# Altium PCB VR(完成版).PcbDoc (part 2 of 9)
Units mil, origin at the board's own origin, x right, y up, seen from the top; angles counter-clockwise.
Board outline 2839.68 x 2020.7 mil, 6 copper layers (TOP, GND02, SIN03, SIN04, PWR05, BOTTOM); 494 components, 404 nets, 7124 pads, 1123 vias.
Unrouted connection lines stored in the file: 10.
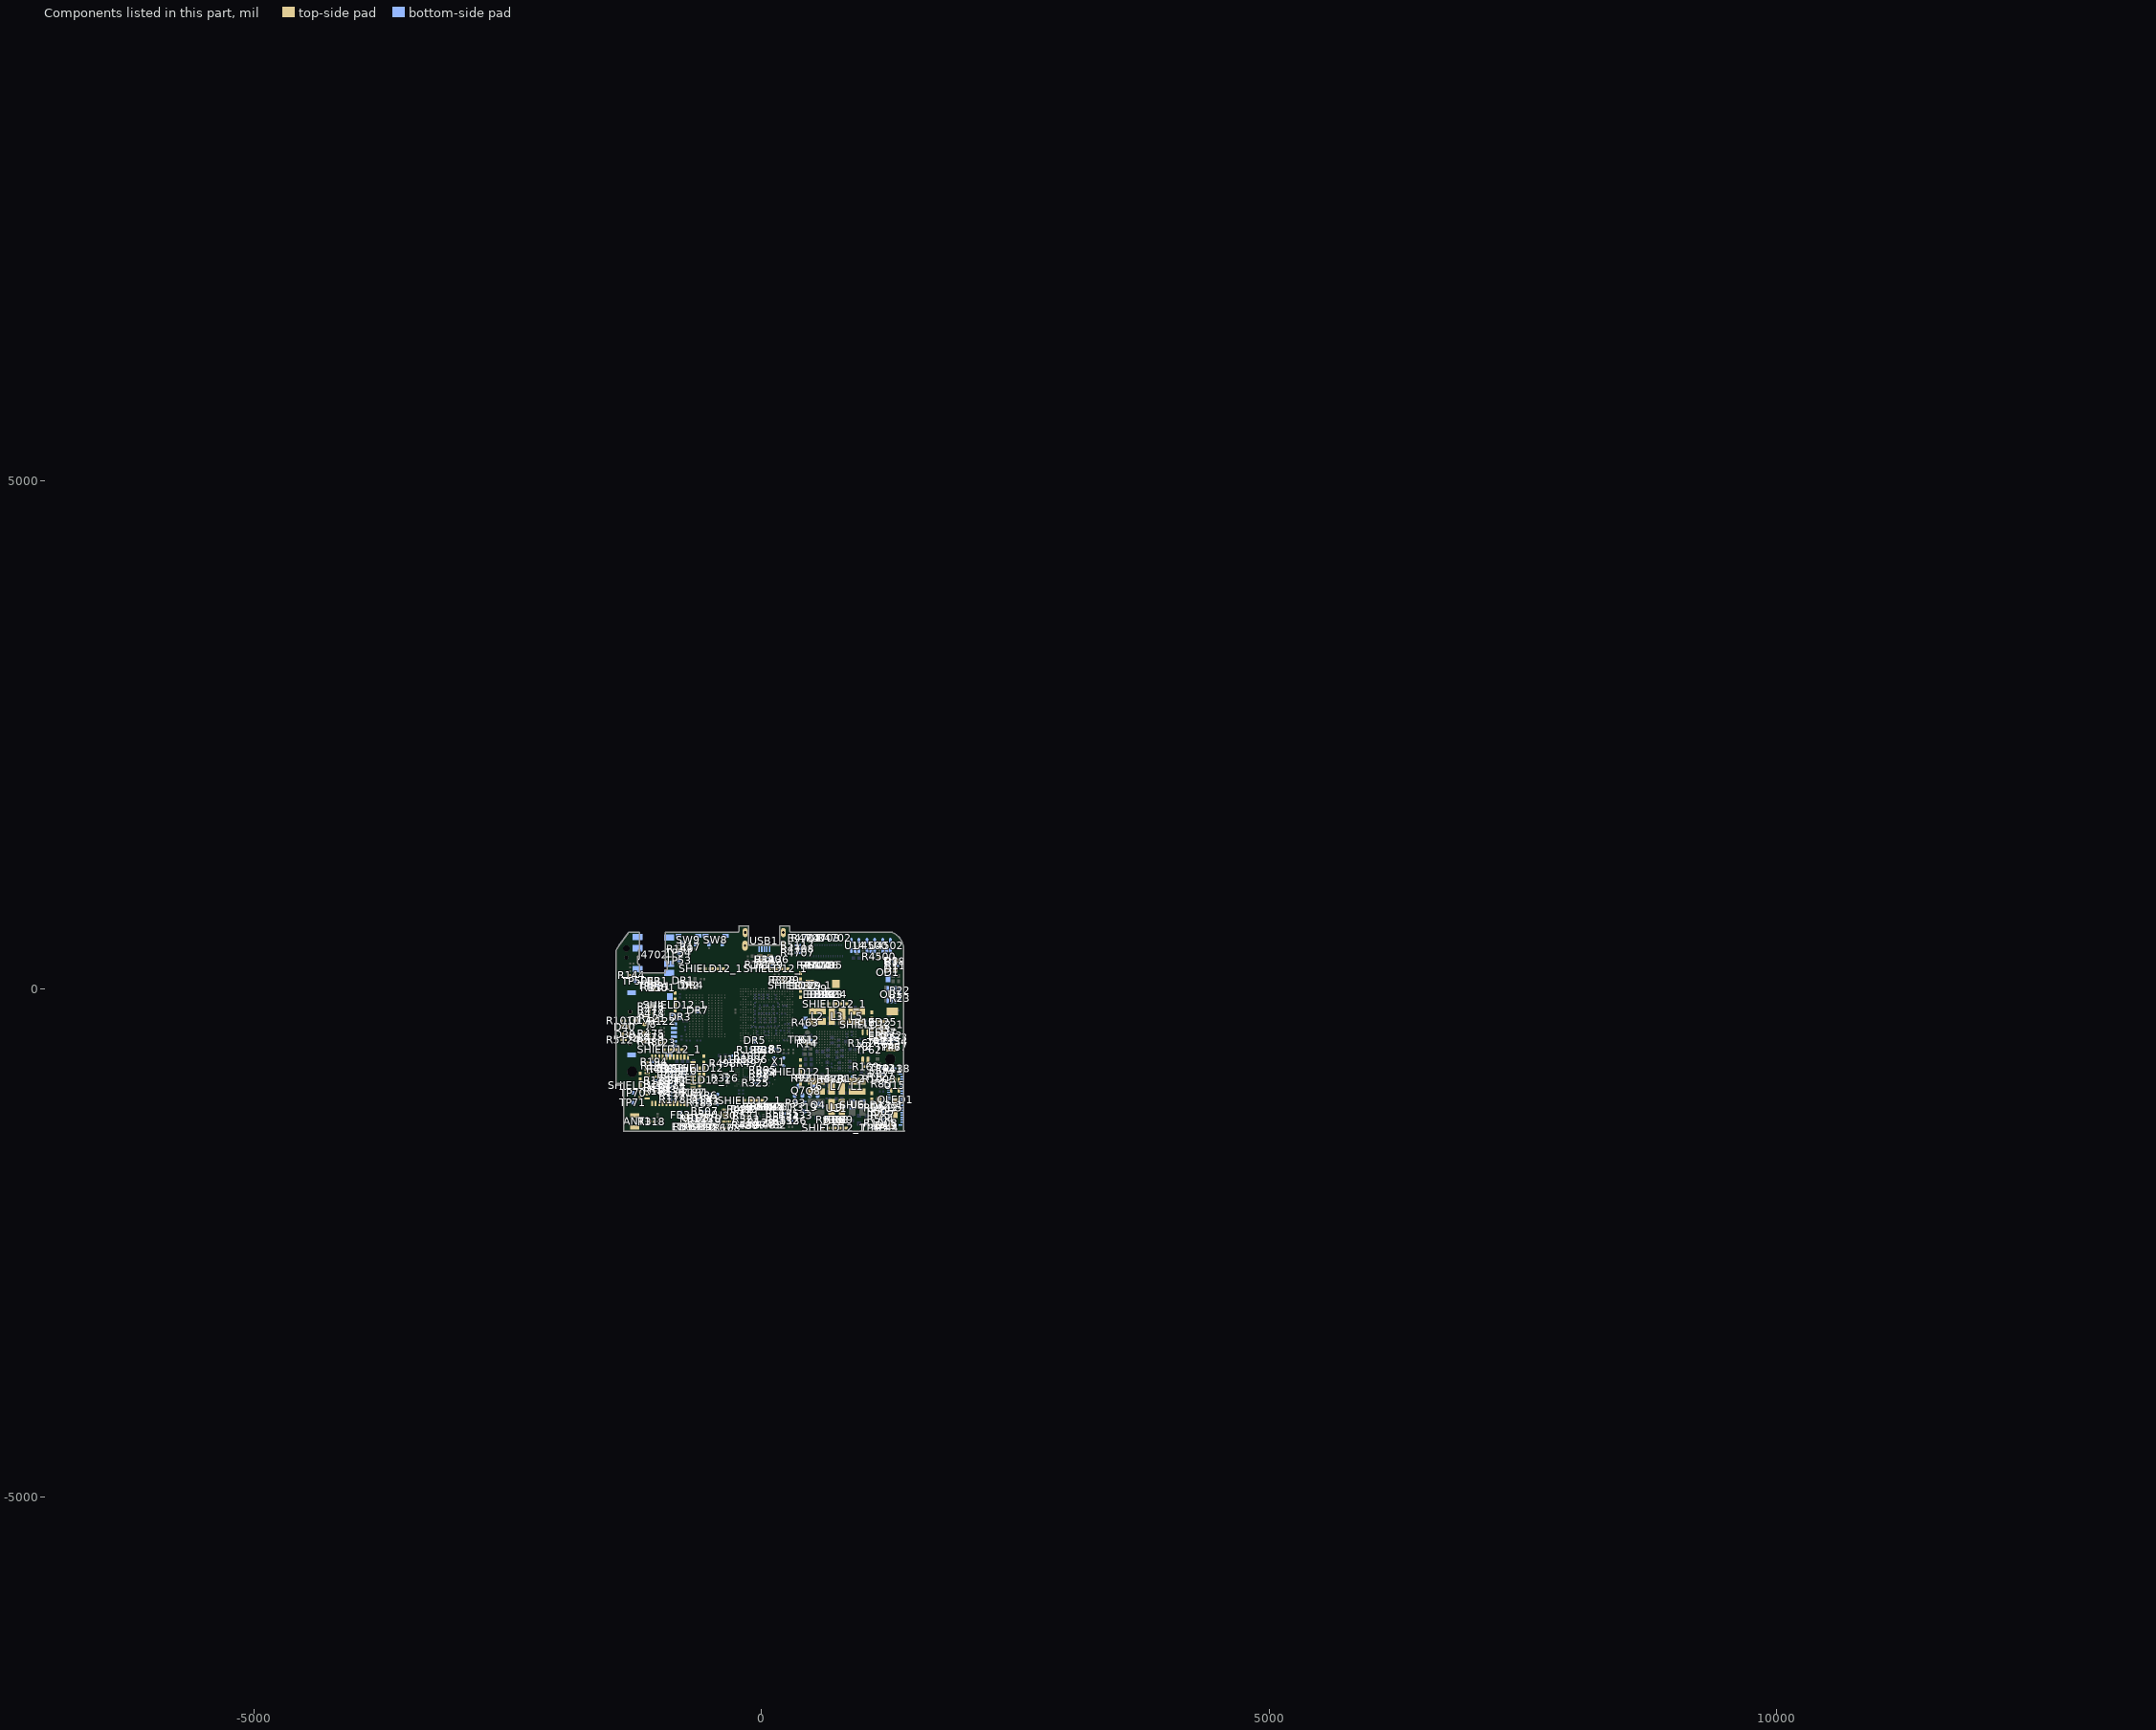
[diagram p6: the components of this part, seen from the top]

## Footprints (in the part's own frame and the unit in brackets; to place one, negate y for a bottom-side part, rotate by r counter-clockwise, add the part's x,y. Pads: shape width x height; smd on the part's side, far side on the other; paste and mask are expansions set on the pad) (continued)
CON2-WIFI-PT4 [mil]
  rect 41.34x41.34 smd: 1(0,30.02)
  rect 41.34x86.61 smd: 2(-58.07,-30.02) 3(58.07,-30.02)
  silkscreen extent -51,-93 51,84
CON39-PT0_6H1_8B [mm] "CON39-PT0_6H1_8B"
  rect 0.3x0.8 smd: 1(-5.7,1.64) 2(-5.4,-1.64) 3(-5.1,1.64) 4(-4.8,-1.64) 5(-4.5,1.64) 6(-4.2,-1.64) 7(-3.9,1.64) 8(-3.6,-1.64) 9(-3.3,1.64) 10(-3,-1.64) 11(-2.7,1.64) 12(-2.4,-1.64) 13(-2.1,1.64) 14(-1.8,-1.64) 15(-1.5,1.64) 16(-1.2,-1.64) 17(-0.9,1.64) 18(-0.6,-1.64) 19(-0.3,1.64) 20(0,-1.64) 21(0.3,1.64) 22(0.6,-1.64) 23(0.9,1.64) 24(1.2,-1.64) 25(1.5,1.64) 26(1.8,-1.64) 27(2.1,1.64) 28(2.4,-1.64) 29(2.7,1.64) 30(3,-1.64) 31(3.3,1.64) 32(3.6,-1.64) 33(3.9,1.64) 34(4.2,-1.64) 35(4.5,1.64) 36(4.8,-1.64) 37(5.1,1.64) 38(5.4,-1.64) 39(5.7,1.64)
  rect 0.35x1 smd: 40(6.35,1.265) 41(-6.35,1.265)
  silkscreen extent -6.65,-1.7 6.65,2.83
CRY-TSX3225 [mil] "CRY-TSX3225"
  oct 33.3x33.3 smd: 1(-37.99,47.83) 2(-37.99,-47.83) 3(37.99,-47.83) 4(37.99,47.83)
  silkscreen extent -90,-67 53,67
DFN8P0_65B2_00X2_00H0_75 [mm]
  rect 0.6x0.4 smd: 1(-1.03,0.65) 2(-1.03,0) 3(-1.03,-0.65) 4(1.03,-0.65) 5(1.03,0) 6(1.03,0.65)
  rect 0.6x0.3 smd: 7(0,-0.65)
  rect 1.05x1 smd: 8(0,0.3)
  silkscreen extent -2.15,-1.14 1.6,1.14
E0402N [mm]
  rect 0.51x0.51 smd: 1(-0.41,0) 2(0.41,0)
  silkscreen extent -1.14,-0.63 0.91,0.64
FPC4-PT1_25-3_8X10H4_6B [mm] "FPC4-PT1_25-3_8X10H4_6B"
  rect 0.85x2.75 smd: 1(-1.875,1.46) 2(-0.625,1.46) 3(0.625,1.46) 4(1.875,1.46)
  rect 2x2.8 smd: 5(-4.5,-1.44) 6(4.5,-1.44)
  silkscreen extent -5,-2.34 5,2.82
FPC8-PT0.5-H1_9A [mm]
  oval 0.3x1.25 smd: 1(0,0) 2(0.5,0) 3(1,0) 4(1.5,0) 5(2,0) 6(2.5,0)
  rect 2x2 smd: 7(4.5,2.29) 8(-2,2.29)
  silkscreen extent -2.99,-1.05 5.48,4.5
L0402 [mm]
  rect 0.51x0.51 smd: 1(-0.41,0) 2(0.41,0)
  silkscreen extent -0.7,-0.5 0.7,0.5
L0603 [mm]
  rect 0.76x0.8 smd: 1(-0.76,0) 2(0.76,0)
  silkscreen extent -1.15,-0.7 1.15,0.7
L3518 [mil] "L3518"
  oval 62.99x110.24 smd: 1(-51.21,0.03) 2(51.15,0.03)
  silkscreen extent -87,-63 87,63
L4018 [mm]
  rect 1.6x4.2 smd: 1(-1.3,0) 2(1.3,0)
  silkscreen extent -2.25,-2.25 2.25,2.25, body extent -1.7,-2.1 1.79,2.09, height 2.2
LED0603 [mm]
  rect 1x1 smd: 1(0.85,0) 2(-0.85,0)
  silkscreen extent -2.28,-0.8 1.65,1.44
LED0805 [mm]
  rect 1.2x1.2 smd: 1(0.95,0) 2(-0.95,0)
  silkscreen extent -2.42,-0.9 1.85,1.49
MICROSD_SLOT [mm]
  rect 0.7x1.6 smd: 1(-2.25,-5.5) 2(-1.15,-5.5) 3(-0.05,-5.5) 4(1.05,-5.5) 5(2.15,-5.5) 6(3.25,-5.5) 7(4.35,-5.5) 8(5.45,-5.5) 9(6.55,-5.5)
  rect 1x1.8 smd: 10(7.75,-4.2)
  rect 1.6x1.5 smd: 11(-6.85,-4.45)
  rect 1.2x2.2 smd: 12(-7.75,5.1) 13(7.75,5.1)
  round 1 hole 1 unplated: ""(-3.05,5.5) ""(4.95,5.5)
  silkscreen extent -8.08,-5 8.08,9.7
MIRCO_USB-5PH3A_DIP [mm] "MIRCO_USB-5PH3A_DIP"
  rect 0.4x1.5 smd: 1(1.3,-2.075) 2(0.65,-2.075) 3(0,-2.075) 4(-0.65,-2.075) 5(-1.3,-2.075)
  oval 1.35x2.5 hole 0.55 slot 1.7 at 90 deg: 6(4.825,-1.225) 7(-4.825,-1.225)
  oval 1.25x2.3 hole 0.65 slot 1.7 at 90 deg: 8(-4.775,2.075) 9(4.775,2.075)
  Keep-Out Layer lines w0.127: 3.809,-0.918 3.809,3.082 ; 3.809,-0.918 -3.791,-0.918 ; 3.809,-0.918 3.809,3.082 ; 3.809,-0.918 -3.791,-0.918 ; 3.809,-0.918 3.809,3.082 ; 3.809,-0.918 -3.791,-0.918 ; 3.809,-0.918 3.809,3.082 ; 3.809,-0.918 -3.791,-0.918 ; 3.809,-0.918 3.809,3.082 ; 3.809,-0.918 -3.791,-0.918 ; 3.809,-0.918 -3.791,-0.918 ; 3.809,-0.918 3.809,3.082 ; -3.791,-0.918 -3.791,3.082 ; -3.791,-0.918 -3.791,3.082 ; -3.791,-0.918 -3.791,3.082 ; -3.791,-0.918 -3.791,3.082 ; -3.791,-0.918 -3.791,3.082 ; -3.791,-0.918 -3.791,3.082
  silkscreen extent -3.81,-1.82 3.8,4.03
MSOP8-PT1-27A [mm]
  rect 1.2x0.4 smd: 1(-2.25,0.975) 2(-2.25,0.325) 3(-2.25,-0.325) 4(-2.25,-0.975) 5(2.25,-0.975) 6(2.25,-0.325) 7(2.25,0.325) 8(2.25,0.975)
  silkscreen extent -1.5,-1.47 1.5,1.48, body extent -1.5,-1.47 1.5,1.48, height 1.2
PJ342 [mm]
  rect 2.5x1.6 smd: 2(-3.95,-4.488) 3(3.95,-4.313) 4(-3.95,-1.663) 5(-3.95,3.538) 6(3.95,2.237) 7(3.95,4.488)
  silkscreen extent -3.7,-9.11 3.7,4.99
QFN24-3X3 [mm] "PS-MPU-6515A-00"
  oval 0.2x0.6 smd: 1(-1,-1.5) 2(-0.6,-1.5) 3(-0.2,-1.5) 4(0.2,-1.5) 5(0.6,-1.5) 6(1,-1.5) 13(1,1.5) 14(0.6,1.5) 15(0.2,1.5) 16(-0.2,1.5) 17(-0.6,1.5) 18(-1,1.5)
  oval 0.6x0.2 smd: 7(1.5,-1) 8(1.5,-0.6) 9(1.5,-0.2) 10(1.5,0.2) 11(1.5,0.6) 12(1.5,1) 19(-1.5,1) 20(-1.5,0.6) 21(-1.5,0.2) 22(-1.5,-0.2) 23(-1.5,-0.6) 24(-1.5,-1)
  rect 1.54x1.7 smd: 25(0,0)
  silkscreen extent -1.6,-2 1.5,1.5
QFN44P0_90B12_00X12_00H1_50 [mm]
  rect 1.3x0.5 smd: 1(-5.775,4.5) 2(-5.775,3.6) 3(-5.775,2.7) 4(-5.775,1.8) 5(-5.775,0.9) 6(-5.775,0) 7(-5.775,-0.9) 8(-5.775,-1.8) 9(-5.775,-2.7) 10(-5.775,-3.6) 11(-5.775,-4.5) 23(5.775,-4.5) 24(5.775,-3.6) 25(5.775,-2.7) 26(5.775,-1.8) 27(5.775,-0.9) 28(5.775,0) 29(5.775,0.9) 30(5.775,1.8) 31(5.775,2.7) 32(5.775,3.6) 33(5.775,4.5)
  rect 0.5x1.3 smd: 12(-4.5,-5.775) 13(-3.6,-5.775) 14(-2.7,-5.775) 15(-1.8,-5.775) 16(-0.9,-5.775) 17(0,-5.775) 18(0.9,-5.775) 19(1.8,-5.775) 20(2.7,-5.775) 21(3.6,-5.775) 22(4.5,-5.775) 34(4.5,5.775) 35(3.6,5.775) 36(2.7,5.775) 37(1.8,5.775) 38(0.9,5.775) 39(0,5.775) 40(-0.9,5.775) 41(-1.8,5.775) 42(-2.7,5.775) 43(-3.6,5.775) 44(-4.5,5.775)
  round 0.6 smd: 45(-2.7,3.6) 46(-0.9,3.6) 47(0.9,3.6)
  silkscreen extent -6.8,-6.8 6.8,6.8, body extent -6,-6 6,6, height 1.6
R0402 [mil] "R0402"
  rect 23.62x23.62 smd: 1(-17.69,0) 2(17.69,0)
  silkscreen extent -33,-16 33,16
R0603 [mil] "R0603"
  rect 31.5x35.43 smd: 1(-28.06,0) 2(27.06,0)
  silkscreen extent -50,-24 50,24
R0805 [mm] "R0805"
  rect 1x1 smd: 1(-1,0) 2(1,0)
  silkscreen extent -1.8,-0.8 1.8,0.8
SOD123 [mm] "SOD123"
  rect 1.8x1.2 smd: 1(-1.6,0) 2(1.6,0)
  silkscreen extent -3.8,-0.9 2.8,1.6
sot23-5 [mm]
  rect 0.6x1.4 smd: 1(-0.95,-1.3) 2(0,-1.3) 3(0.95,-1.3) 4(0.95,1.3) 5(-0.95,1.3)
  silkscreen extent -1.5,-2.75 1.5,0.3
SOT23-5 [mm]
  rect 0.6x1.4 smd: 1(-0.95,-1.3) 2(0,-1.3) 3(0.95,-1.3) 4(0.95,1.3) 5(-0.95,1.3)
  silkscreen extent -2.1,-2.17 1.5,0.3
SOT23-6 [mm] "SOT23-6"
  oval 0.6x1.25 smd: 1(-0.95,-1.52) 2(0,-1.52) 3(0.95,-1.52) 4(0.95,1.53) 5(0,1.53) 6(-0.95,1.53)
  silkscreen extent -1.88,-1.54 1.5,0.86
SOT23_5H14A [mil] "SOT23_5H14A"
  oval 50x26 smd: 1(-50,37.5) 2(-50,0) 3(-50,-37.5) 4(50,-37.5) 5(50,37.5)
  silkscreen extent -86,-64 36,73
SOT-23 [mil] "SOT-23"
  oval 50x40 smd: 1(-45,37.5) 2(-45,-37.5) 3(45,0)
  silkscreen extent -29,-63 29,73
SW4_SMD [mm]
  rect 0.8x1.3 smd: 1(1.7,-0.975) 2(-1.7,-0.975)
  rect 1.5x1 smd: 3(-2.5,0.975) 4(2.5,0.975)
  round 0.7 hole 0.7 unplated: 5(-0.8,0.475) 6(0.8,0.475)
  silkscreen extent -2.33,-0.62 2.34,2.08
TEST2 [mm]
  rect 1.4x0.7 smd far side: 1(0,0)
  rect 0.8x0.7 smd far side: 2(-1.5,0) 4(1.5,0)
  rect 0.9x0.7 smd far side: 3(-3,0) 5(3,0)
TP40_SMD [mm] "TP40_SMD"
  round 1 smd: 1(0,0)
  silkscreen extent -0.6,-0.6 0.6,0.6
TP_SMD [mil] "TP_SMD"
  round 40 smd: 1(0,0)
  silkscreen extent -26,-26 26,26
XCOL-SMD [mm]
  round 0.5 on Top Overlay: 0(-2.223,0.653)
  oval 1.8x0.8 smd: 1(-3.5,0.647) 2(-3.5,-0.653)
  oval 1.5x0.5 smd: 3(3.5,0.647) 4(3.5,-0.553)
  silkscreen extent -2.6,-0.95 2.7,1.05, body extent -2.6,-0.95 2.7,1.05, height 1.5

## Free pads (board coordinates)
  round 39.37 hole 39.37 unplated: 0(-1329.63,307.82)
  round 62.99 hole 62.99 unplated: 0(-1329.63,398.37)
  round 102.36 hole 102.36 unplated: 0(-1270.58,-817.05) 0(1268.8,-692.18)
  round 11.8 on Drill Drawing: 1(-6737.21,-6759.26) 1(-6737.21,-6759.26) 1(-6737.21,9185.04) 1(-6737.21,9186.21) 1(-6146.65,-3215.96) 1(-6146.65,-263.2) 1(-6146.65,2689.56) 1(-6146.65,5642.33) 1(-5851.37,5524.22) 1(-5851.37,5524.22) 1(-5851.37,5642.33) 1(-5851.37,5760.44) 1(-5851.37,5760.44) 1(-5556.1,-6168.71) 1(-5556.1,-6168.71) 1(-5556.1,-3215.96) 1(-5556.1,-263.2) 1(-5556.1,2689.56) 1(-5556.1,5642.33) 1(-5556.1,5642.33) 1(-5556.1,8593.89) 1(-5556.1,8595.66) 1(-2603.35,-6759.26) 1(-2603.35,-6168.71) 1(-1507.86,8595.66) 1(-1507.86,9186.21) 1(349.41,-6759.26) 1(349.41,-6168.71) 1(1444.89,8595.66) 1(1444.89,9186.21) 1(3302.18,-6759.26) 1(3302.18,-6168.71) 1(4397.64,8595.66) 1(4397.64,9186.21) 1(6254.93,-6759.26) 1(6254.93,-6168.71) 1(6254.93,8595.66) 1(6254.93,9186.21) 1(7428.47,6343.47) 1(7428.47,6343.47) 1(7428.47,6433.23) 1(7428.47,6433.23) 1(7428.47,6693.47) 1(7428.47,6693.47) 1(7428.47,6783.23) 1(7428.47,6783.23) 1(7428.47,6843.47) 1(7428.47,6843.47) 1(7428.47,6933.23) 1(7428.47,6933.23) 1(7428.67,6198.47) 1(7428.67,6198.47) 1(7428.67,6288.23) 1(7428.67,6288.23) 1(7518.23,6343.47) 1(7518.23,6343.47) 1(7518.23,6433.23) 1(7518.23,6433.23) 1(7518.23,6693.47) 1(7518.23,6693.47) 1(7518.23,6783.23) 1(7518.23,6783.23) 1(7518.23,6843.47) 1(7518.23,6843.47) 1(7518.23,6933.23) 1(7518.23,6933.23) 1(7518.43,6198.47) 1(7518.43,6198.47) 1(7518.43,6288.23) 1(7518.43,6288.23) 1(8103.67,6043.47) 1(8103.67,6043.47) 1(8103.67,6133.23) 1(8103.67,6133.23) 1(8193.43,6043.47) 1(8193.43,6043.47) 1(8193.43,6133.23) 1(8193.43,6133.23) 1(8728.47,7293.47) 1(8728.47,7293.47) 1(8728.47,7383.23) 1(8728.47,7383.23) 1(8818.23,7293.47) 1(8818.23,7293.47) 1(8818.23,7383.23) 1(8818.23,7383.23) 1(9207.7,-6759.26) 1(9207.7,-6168.71) 1(9207.7,8595.66) 1(9207.7,9186.21) 1(10078.47,5743.47) 1(10078.47,5743.47) 1(10078.47,5833.23) 1(10078.47,5833.23) 1(10168.23,5743.47) 1(10168.23,5743.47) 1(10168.23,5833.23) 1(10168.23,5833.23) 1(12042.34,-6464.57) 1(12042.34,-6464.57) 1(12159.27,-6168.71) 1(12160.45,-6759.26) 1(12160.45,-6464.57) 1(12160.45,-6168.71) 1(12160.45,-6168.71) 1(12160.45,-6168.71) 1(12160.45,-3215.96) 1(12160.45,-263.2) 1(12160.45,2689.56) 1(12160.45,5642.33) 1(12160.45,5642.33) 1(12160.45,8595.66) 1(12160.45,8595.66) 1(12278.56,-6464.57) 1(12278.56,-6464.57) 1(12455.73,5524.22) 1(12455.73,5524.22) 1(12455.73,5642.33) 1(12455.73,5760.44) 1(12455.73,5760.44) 1(12751,-3215.96) 1(12751,-263.2) 1(12751,2689.56) 1(12751,5642.33) 1(13340.97,-6759.26) 1(13340.97,9186.21) 1(13341.55,-6759.26) 1(13341.55,9185.04)
  round 8 on Drill Drawing: 1(-6126.84,-5039.7) 1(-6126.84,-4939.7) 1(-6126.84,-4839.7) 1(-6089.34,-1749.7) 1(-6089.34,-1749.7) 1(-6089.34,-1726.37) 1(-6089.34,-1726.37) 1(-6084.34,-1776.37) 1(-6084.34,-1776.37) 1(-6084.34,-1706.37) 1(-6084.34,-1706.37) 1(-6079.34,7060.31) 1(-6079.34,7060.31) 1(-6079.34,7260.31) 1(-6079.34,7260.31) 1(-6074.34,-1799.7) 1(-6074.34,-1799.7) 1(-6074.34,-1683.03) 1(-6074.34,-1683.03) 1(-6074.34,4010.31) 1(-6074.34,4010.31) 1(-6074.34,4113.65) 1(-6074.34,4210.31) 1(-6074.34,4210.31) 1(-6071.84,960.3) 1(-6071.84,1063.64) 1(-6071.84,1160.3) 1(-6071.84,1160.3) 1(-6059.34,-1819.7) 1(-6059.34,-1819.7) 1(-6059.34,-1663.03) 1(-6059.34,-1663.03) 1(-6044.34,-1649.7) 1(-6044.34,-1649.7) 1(-6041.84,-1833.04) 1(-6041.84,-1833.04) 1(-6029.34,7060.31) 1(-6029.34,7060.31) 1(-6029.34,7260.31) 1(-6029.34,7260.31) 1(-6024.34,-1639.7) 1(-6024.34,-1639.7) 1(-6021.84,-5039.7) 1(-6021.84,-4939.7) 1(-6021.84,-4839.7) 1(-6016.84,-1839.7) 1(-6016.84,-1839.7) 1(-6014.34,4113.65) 1(-6011.84,1063.64) 1(-6009.34,-1739.7) 1(-6009.34,7070.31) 1(-6009.34,7070.31) 1(-6009.34,7250.31) 1(-6009.34,7250.31) 1(-6006.84,-1639.7) 1(-6006.84,-1639.7) 1(-5994.34,7083.64) 1(-5994.34,7083.64) 1(-5994.34,7236.98) 1(-5994.34,7236.98) 1(-5991.84,-1833.04) 1(-5991.84,-1833.04) 1(-5986.84,-1646.36) 1(-5986.84,-1646.36) 1(-5981.84,7103.64) 1(-5981.84,7103.64) 1(-5981.84,7216.98) 1(-5981.84,7216.98) 1(-5976.84,1160.3) 1(-5974.34,-1819.7) 1(-5974.34,-1819.7) 1(-5974.34,4010.31) 1(-5974.34,4210.31) 1(-5971.84,-1659.7) 1(-5971.84,7126.97) 1(-5971.84,7126.97) 1(-5971.84,7193.64) 1(-5971.84,7193.64) 1(-5969.34,7160.31) 1(-5969.34,7160.31) 1(-5959.34,-1799.7) 1(-5959.34,-1799.7) 1(-5959.34,-1739.7) 1(-5959.34,-1739.7) 1(-4154.34,-6539.7) 1(-4154.34,-6379.7) 1(-4124.34,-6539.7) 1(-4124.34,-6339.7) 1(-4124.34,-6339.7) 1(-4094.34,-6539.7) 1(-3754.34,8810.31) 1(-3754.34,8970.31) 1(-3724.34,8810.31) 1(-3724.34,9010.31) 1(-3724.34,9010.31) 1(-3694.34,8810.31) 1(-1076.83,-6539.7) 1(-1076.83,-6539.7) 1(-1071.83,-6509.71) 1(-1071.83,-6509.71) 1(-1071.83,-6373.03) 1(-1056.83,-6476.37) 1(-1056.83,-6476.37) 1(-1056.83,-6353.04) 1(-1056.83,-6353.04) 1(-1039.33,-6343.03) 1(-1039.33,-6343.03) 1(-1034.33,-6453.03) 1(-1034.33,-6453.03) 1(-1019.33,-6339.7) 1(-1019.33,-6339.7) 1(-994.33,-6346.36) 1(-994.33,-6346.36) 1(-984.33,-6419.7) 1(-984.33,-6419.7) 1(-976.83,-6363.03) 1(-976.83,-6363.03) 1(-974.33,-6403.04) 1(-974.33,-6403.04) 1(-971.83,-6539.7) 1(-971.83,-6383.03) 1(-971.83,-6383.03) 1(-76.83,8810.31) 1(-76.83,8810.31) 1(-71.83,8840.3) 1(-71.83,8840.3) 1(-71.83,8976.98) 1(-56.83,8873.64) 1(-56.83,8873.64) 1(-56.83,8996.97) 1(-56.83,8996.97) 1(-39.33,9006.98) 1(-39.33,9006.98) 1(-34.33,8896.98) 1(-34.33,8896.98) 1(-19.33,9010.31) 1(-19.33,9010.31) 1(5.67,9003.64) 1(5.67,9003.64) 1(15.67,8930.31) 1(15.67,8930.31) 1(23.17,8986.98) 1(23.17,8986.98) 1(25.67,8946.97) 1(25.67,8946.97) 1(28.17,8810.31) 1(28.17,8966.98) 1(28.17,8966.98) 1(1670.67,-6549.7) 1(1685.67,-6573.04) 1(1685.67,-6573.04) 1(1690.67,-6406.37) 1(1705.67,-6586.37) 1(1705.67,-6586.37) 1(1713.17,-6393.03) 1(1713.17,-6393.03) 1(1720.67,-6483.03) 1(1728.17,-6589.7) 1(1728.17,-6589.7) 1(1735.67,-6389.7) 1(1735.67,-6389.7) 1(1743.17,-6483.03) 1(1743.17,-6483.03) 1(1743.17,-6483.03) 1(1748.17,-6586.37) 1(1748.17,-6586.37) 1(1758.17,-6473.03) 1(1758.17,-6473.03) 1(1758.17,-6399.7) 1(1758.17,-6399.7) 1(1760.67,-6489.7) 1(1760.67,-6489.7) 1(1768.17,-6569.7) 1(1768.17,-6569.7) 1(1770.67,-6456.37) 1(1770.67,-6456.37) 1(1770.67,-6416.37) 1(1770.67,-6416.37) 1(1775.67,-6436.37) 1(1775.67,-6436.37) 1(1778.17,-6506.37) 1(1778.17,-6506.37) 1(1780.67,-6549.7) 1(1780.67,-6549.7) 1(1783.17,-6529.7) 1(1783.17,-6529.7) 1(2970.67,8850.31) 1(2985.67,8826.97) 1(2985.67,8826.97) 1(2990.67,8993.64) 1(3005.67,8813.64) 1(3005.67,8813.64) 1(3013.17,9006.98) 1(3013.17,9006.98) 1(3020.67,8916.98) 1(3028.17,8810.31) 1(3028.17,8810.31) 1(3035.67,9010.31) 1(3035.67,9010.31) 1(3043.17,8916.98) 1(3043.17,8916.98) 1(3043.17,8916.98) 1(3048.17,8813.64) 1(3048.17,8813.64) 1(3058.17,8926.98) 1(3058.17,8926.98) 1(3058.17,9000.31) 1(3058.17,9000.31) 1(3060.67,8910.31) 1(3060.67,8910.31) 1(3068.17,8830.31) 1(3068.17,8830.31) 1(3070.67,8943.64) 1(3070.67,8943.64) 1(3070.67,8983.64) 1(3070.67,8983.64) 1(3075.67,8963.64) 1(3075.67,8963.64) 1(3078.17,8893.64) 1(3078.17,8893.64) 1(3080.67,8850.31) 1(3080.67,8850.31) 1(3083.17,8870.31) 1(3083.17,8870.31) 1(4663.17,-6533.03) 1(4663.17,-6533.03) 1(4755.67,-6589.7) 1(4755.67,-6389.7) 1(4755.67,-6389.7) 1(4788.17,-6533.03) 1(5263.17,8866.98) 1(5263.17,8866.98) 1(5355.67,8810.31) 1(5355.67,9010.31) 1(5355.67,9010.31) 1(5388.17,8866.98) 1(7322.11,-2621.85) 1(7322.11,-2621.85) 1(7322.11,-2546.85) 1(7322.11,-2546.85) 1(7340.77,-2621.85) 1(7340.77,-2621.85) 1(7340.77,-2546.85) 1(7340.77,-2546.85) 1(7348.24,-2618.1) 1(7348.24,-2618.1) 1(7348.24,-2550.6) 1(7348.24,-2550.6) 1(7353.84,-2613.1) 1(7353.84,-2613.1) 1(7353.84,-2555.6) 1(7353.84,-2555.6) 1(7358.51,-2605.6) 1(7358.51,-2605.6) 1(7358.51,-2563.1) 1(7358.51,-2563.1) 1(7362.24,-2596.85) 1(7362.24,-2596.85) 1(7362.24,-2571.85) 1(7362.24,-2571.85) 1(7363.17,-2584.35) 1(7363.17,-2584.35) 1(7406.44,-2621.85) 1(7406.44,-2546.85) 1(7417.64,-2621.85) 1(7417.64,-2546.85) 1(7428.84,-2621.85) 1(7428.84,-2546.85) 1(7474.91,-2621.85) 1(7474.91,-2583.1) 1(7474.91,-2546.85) 1(7474.91,-2546.85) 1(7497.31,-2583.1) 1(7510.37,-2546.85) 1(7523.52,-573.08) 1(7527.25,-526.83) 1(7527.25,-526.83) 1(7529.12,-518.08) 1(7529.12,-518.08) 1(7530.05,-535.58) 1(7530.05,-535.58) 1(7530.99,-579.33) 1(7530.99,-579.33) 1(7533.79,-511.83) 1(7533.79,-511.83) 1(7536.59,-540.58) 1(7536.59,-540.58) 1(7539.39,-583.08) 1(7539.39,-583.08) 1(7540.32,-508.08) 1(7540.32,-508.08) 1(7546.85,-583.08) 1(7546.85,-583.08) 1(7546.85,-508.08) 1(7546.85,-508.08) 1(7547.79,-543.08) 1(7547.79,-543.08) 1(7549.91,-2621.85) 1(7549.91,-2583.1) 1(7549.91,-2546.85) 1(7549.91,-2546.85) 1(7553.39,-510.58) 1(7553.39,-510.58) 1(7554.32,-579.33) 1(7554.32,-579.33) 1(7556.19,-548.08) 1(7556.19,-548.08) 1(7558.99,-516.83) 1(7559.92,-573.08) 1(7559.92,-573.08) 1(7560.85,-555.58) 1(7560.85,-555.58) 1(7562.72,-564.33) 1(7562.72,-564.33) 1(7572.31,-2583.1) 1(7585.37,-2546.85) 1(7606.92,-583.08) 1(7606.92,-508.08) 1(7618.12,-583.08) 1(7618.12,-508.08) 1(7623.97,-2621.85) 1(7623.97,-2621.85) 1(7623.97,-2583.1) 1(7623.97,-2546.85) 1(7623.97,-2546.85) 1(7629.32,-583.08) 1(7629.32,-508.08) 1(7646.37,-2583.1) 1(7661.31,-2621.85) 1(7661.31,-2546.85) 1(7671.65,-583.08) 1(7671.65,-508.08) 1(7671.65,-508.08) 1(7698.97,-2621.85) 1(7698.97,-2585.6) 1(7698.97,-2546.85) 1(7698.97,-2546.85) 1(7714.59,-583.08) 1(7714.59,-583.08) 1(7714.59,-508.08) 1(7722.31,-2585.6) 1(7722.31,-2585.6) 1(7722.31,-2585.6) 1(7722.31,-2546.85) 1(7722.31,-2546.85) 1(7728.84,-2581.85) 1(7728.84,-2581.85) 1(7729.77,-2550.6) 1(7729.77,-2550.6) 1(7734.44,-2575.6) 1(7734.44,-2575.6) 1(7734.44,-2555.6) 1(7734.44,-2555.6) 1(7736.31,-2621.85) 1(7736.31,-2565.6) 1(7736.31,-2565.6) 1(7743.85,-549.33) 1(7743.85,-549.33) 1(7743.85,-540.58) 1(7743.85,-540.58) 1(7745.72,-559.33) 1(7745.72,-559.33) 1(7745.72,-533.08) 1(7745.72,-533.08) 1(7749.45,-568.08) 1(7749.45,-568.08) 1(7749.45,-524.33) 1(7749.45,-524.33) 1(7755.05,-575.58) 1(7755.05,-575.58) 1(7755.05,-516.83) 1(7755.05,-516.83) 1(7760.65,-511.83) 1(7760.65,-511.83) 1(7761.59,-580.58) 1(7761.59,-580.58) 1(7768.12,-508.08) 1(7768.12,-508.08) 1(7770.68,8840.3) 1(7770.92,-583.08) 1(7770.92,-583.08) 1(7773.72,-545.58) 1(7773.97,-2621.85) 1(7773.97,-2621.85) 1(7773.97,-2583.1) 1(7773.97,-2546.85) 1(7773.97,-2546.85) 1(7774.65,-508.08) 1(7774.65,-508.08) 1(7780.25,-580.58) 1(7780.25,-580.58) 1(7782.12,-510.58) 1(7782.12,-510.58) 1(7785.68,8823.64) 1(7785.68,8823.64) 1(7786.79,-575.58) 1(7786.79,-575.58) 1(7787.72,-515.58) 1(7788.18,8923.64) 1(7788.18,8923.64) 1(7792.39,-568.08) 1(7792.39,-568.08) 1(7792.39,-545.58) 1(7792.39,-545.58) 1(7795.68,9010.31) 1(7795.68,9010.31) 1(7796.37,-2583.1) 1(7803.18,8813.64) 1(7803.18,8813.64) 1(7810.68,8936.97) 1(7810.68,8936.97) 1(7811.31,-2621.85) 1(7811.31,-2546.85) 1(7820.68,-6509.71) 1(7824.45,-583.08) 1(7824.45,-583.08) 1(7824.45,-508.08) 1(7825.68,8810.31) 1(7825.68,8810.31) 1(7828.18,8940.31) 1(7828.18,8940.31) 1(7835.68,-6526.37) 1(7835.68,-6526.37) 1(7838.18,-6426.37) 1(7838.18,-6426.37) 1(7845.68,-6339.7) 1(7845.68,-6339.7) 1(7845.68,8936.97) 1(7845.68,8936.97) 1(7846.17,-2621.85) 1(7846.17,-2546.85) 1(7846.17,-2546.85) 1(7848.18,8816.97) 1(7848.18,8816.97) 1(7853.18,-6536.37) 1(7853.18,-6536.37) 1(7860.68,-6413.04) 1(7860.68,-6413.04) 1(7861.79,-583.08) 1(7863.18,8923.64) 1(7863.18,8923.64) 1(7863.18,9010.31) 1(7865.68,8830.31) 1(7865.68,8830.31) 1(7875.68,-6539.7) 1(7875.68,-6539.7) 1(7875.68,8906.97) 1(7875.68,8906.97) 1(7878.18,-6409.7) 1(7878.18,-6409.7) 1(7878.18,8853.64) 1(7878.18,8853.64) 1(7880.68,8880.31) 1(7880.68,8880.31) 1(7889.11,-2621.85) 1(7889.11,-2621.85) 1(7889.11,-2546.85) 1(7895.68,-6413.04) 1(7895.68,-6413.04) 1(7898.18,-6533.04) 1(7898.18,-6533.04) 1(7899.45,-583.08) 1(7899.45,-583.08) 1(7899.45,-544.33) 1(7899.45,-508.08) 1(7899.45,-508.08) 1(7913.18,-6426.37) 1(7913.18,-6426.37) 1(7913.18,-6339.7) 1(7915.68,-6519.7) 1(7915.68,-6519.7) 1(7921.17,-2546.85) 1(7921.85,-544.33) 1(7925.68,-6443.04) 1(7925.68,-6443.04) 1(7928.18,-6496.37) 1(7928.18,-6496.37) 1(7930.68,-6469.7) 1(7930.68,-6469.7) 1(7936.79,-583.08) 1(7936.79,-508.08) 1(7942.64,-2621.85) 1(7942.64,-2546.85) 1(7964.11,-2546.85) 1(8006.44,-2546.85) 1(8017.64,-2621.85) 1(8017.64,-2546.85) 1(8028.84,-2546.85) 1(8046.65,-508.08) 1(8068.12,-583.08) 1(8068.12,-508.08) 1(8068.25,-2634.06) 1(8069.31,-2621.85) 1(8077.71,-2595.6) 1(8089.59,-508.08) 1(8090.65,-2634.06) 1(8092.64,-2546.85) 1(8092.64,-2546.85) 1(8107.57,-2595.6) 1(8115.97,-2621.85) 1(8124.45,-583.08) 1(8124.45,-546.83) 1(8124.45,-508.08) 1(8124.45,-508.08) 1(8147.79,-546.83) 1(8147.79,-546.83) 1(8147.79,-546.83) 1(8147.79,-508.08) 1(8147.79,-508.08) 1(8148.97,-2621.85) 1(8148.97,-2621.85) 1(8148.97,-2546.85) 1(8154.32,-543.08) 1(8154.32,-543.08) 1(8155.25,-511.83) 1(8155.25,-511.83) 1(8159.92,-536.83) 1(8159.92,-536.83) 1(8159.92,-516.83) 1(8159.92,-516.83) 1(8161.79,-583.08) 1(8161.79,-526.83) 1(8161.79,-526.83) 1(8186.31,-2621.85) 1(8194.79,-583.08) 1(8203.19,-556.83) 1(8218.12,-508.08) 1(8218.12,-508.08) 1(8233.05,-556.83) 1(8241.45,-583.08) 1(8269.79,-549.33) 1(8269.79,-549.33) 1(8270.72,-538.08) 1(8270.72,-538.08) 1(8271.65,-560.58) 1(8271.65,-560.58) 1(8274.45,-568.08) 1(8274.45,-568.08) 1(8274.45,-525.58) 1(8274.45,-525.58) 1(8279.12,-518.08) 1(8279.12,-518.08) 1(8280.05,-575.58) 1(8280.05,-575.58) 1(8285.65,-511.83) 1(8285.65,-511.83) 1(8286.59,-580.58) 1(8286.59,-580.58) 1(8293.12,-583.08) 1(8293.12,-583.08) 1(8294.05,-508.08) 1(8294.05,-508.08) 1(8296.17,-2546.85) 1(8299.65,-583.08) 1(8299.65,-583.08) 1(8301.52,-508.08) 1(8301.52,-508.08) 1(8306.19,-580.58) 1(8306.19,-580.58) 1(8308.05,-510.58) 1(8308.05,-510.58) 1(8311.79,-576.83) 1(8311.79,-576.83) 1(8313.65,-514.33) 1(8316.45,-571.83) 1(8317.64,-2621.85) 1(8317.64,-2546.85) 1(8339.11,-2546.85) 1(8349.45,-583.08) 1(8349.45,-583.08) 1(8349.45,-544.33) 1(8349.45,-508.08) 1(8349.45,-508.08) 1(8371.85,-544.33) 1(8373.97,-2621.85) 1(8373.97,-2585.6) 1(8373.97,-2546.85) 1(8373.97,-2546.85) 1(8386.79,-583.08) 1(8386.79,-508.08) 1(8397.31,-2585.6) 1(8397.31,-2585.6) 1(8397.31,-2585.6) 1(8397.31,-2546.85) 1(8397.31,-2546.85) 1(8403.84,-2581.85) 1(8403.84,-2581.85) 1(8404.77,-2550.6) 1(8404.77,-2550.6) 1(8409.44,-2575.6) 1(8409.44,-2575.6) 1(8409.44,-2555.6) 1(8409.44,-2555.6) 1(8411.31,-2621.85) 1(8411.31,-2565.6) 1(8411.31,-2565.6) 1(8444.31,-2621.85) 1(8452.71,-2595.6) 1(8467.64,-2546.85) 1(8467.64,-2546.85) 1(8482.57,-2595.6) 1(8490.97,-2621.85) 1(8506.92,-583.08) 1(8506.92,-508.08) 1(8518.12,-583.08) 1(8518.12,-508.08) 1(8519.31,-2588.1) 1(8519.31,-2588.1) 1(8520.24,-2576.85) 1(8520.24,-2576.85) 1(8521.17,-2599.35) 1(8521.17,-2599.35) 1(8523.97,-2606.85) 1(8523.97,-2606.85) 1(8523.97,-2564.35) 1(8523.97,-2564.35) 1(8528.64,-2556.85) 1(8528.64,-2556.85) 1(8529.32,-583.08) 1(8529.32,-508.08) 1(8529.57,-2614.35) 1(8529.57,-2614.35) 1(8535.17,-2550.6) 1(8535.17,-2550.6) 1(8536.11,-2619.35) 1(8536.11,-2619.35) 1(8542.64,-2621.85) 1(8542.64,-2621.85) 1(8543.57,-2546.85) 1(8543.57,-2546.85) 1(8549.17,-2621.85) 1(8549.17,-2621.85) 1(8551.04,-2546.85) 1(8551.04,-2546.85) 1(8555.71,-2619.35) 1(8555.71,-2619.35) 1(8557.57,-2549.35) 1(8557.57,-2549.35) 1(8561.31,-2615.6) 1(8561.31,-2615.6) 1(8563.17,-2553.1) 1(8565.97,-2610.6) 1(8568.85,-583.08) 1(8568.85,-508.08) 1(8568.85,-508.08) 1(8593.12,-570.58) 1(8593.12,-570.58) 1(8598.97,-2621.85) 1(8598.97,-2621.85) 1(8598.97,-2583.1) 1(8598.97,-2546.85) 1(8598.97,-2546.85) 1(8617.39,-583.08) 1(8617.39,-508.08) 1(8617.39,-508.08) 1(8621.37,-2583.1) 1(8636.31,-2621.85) 1(8636.31,-2546.85) 1(8649.45,-583.08) 1(8649.45,-551.83) 1(8649.45,-508.08) 1(8649.45,-508.08) 1(8671.85,-551.83) 1(8671.85,-551.83) 1(8671.85,-508.08) 1(8671.85,-508.08) 1(8679.32,-511.83) 1(8679.32,-511.83) 1(8680.25,-548.08) 1(8680.25,-548.08) 1(8684.92,-540.58) 1(8684.92,-540.58) 1(8684.92,-520.58) 1(8684.92,-520.58) 1(8686.79,-530.58) 1(8686.79,-530.58) 1(8724.45,-583.08) 1(8724.45,-583.08) 1(8724.45,-544.33) 1(8724.45,-508.08) 1(8724.45,-508.08) 1(8746.85,-544.33) 1(8756.44,-2621.85) 1(8756.44,-2546.85) 1(8761.79,-583.08) 1(8761.79,-508.08) 1(8767.64,-2621.85) 1(8767.64,-2546.85) 1(8778.84,-2621.85) 1(8778.84,-2546.85) 1(8797.59,-583.08) 1(8797.59,-583.08) 1(8797.59,-508.08) 1(8797.59,-508.08) 1(8816.25,-583.08) 1(8816.25,-583.08) 1(8816.25,-508.08) 1(8816.25,-508.08) 1(8818.37,-2621.85) 1(8818.37,-2546.85) 1(8818.37,-2546.85) 1(8823.72,-579.33) 1(8823.72,-579.33) 1(8823.72,-511.83) 1(8823.72,-511.83) 1(8829.32,-574.33) 1(8829.32,-574.33) 1(8829.32,-516.83) 1(8829.32,-516.83) 1(8833.99,-566.83) 1(8833.99,-566.83) 1(8833.99,-524.33) 1(8833.99,-524.33) 1(8837.72,-558.08) 1(8837.72,-558.08) 1(8837.72,-533.08) 1(8837.72,-533.08) 1(8838.65,-545.58) 1(8838.65,-545.58) 1(8842.64,-2609.35) 1(8842.64,-2609.35) 1(8866.91,-2621.85) 1(8866.91,-2546.85) 1(8866.91,-2546.85) 1(8869.79,-583.08) 1(8878.19,-556.83) 1(8893.12,-508.08) 1(8893.12,-508.08) 1(8898.97,-2621.85) 1(8898.97,-2590.6) 1(8898.97,-2546.85) 1(8898.97,-2546.85) 1(8908.05,-556.83) 1(8916.45,-583.08) 1(8921.37,-2590.6) 1(8921.37,-2590.6) 1(8921.37,-2546.85) 1(8921.37,-2546.85) 1(8928.84,-2550.6) 1(8928.84,-2550.6) 1(8929.77,-2586.85) 1(8929.77,-2586.85) 1(8934.44,-2579.35) 1(8934.44,-2579.35) 1(8934.44,-2559.35) 1(8934.44,-2559.35) 1(8936.31,-2569.35) 1(8936.31,-2569.35) 1(8946.65,-583.08) 1(8946.65,-508.08) 1(8946.65,-508.08) 1(8973.97,-2621.85) 1(8973.97,-2621.85) 1(8973.97,-2583.1) 1(8973.97,-2546.85) 1(8973.97,-2546.85) 1(8989.59,-583.08) 1(8989.59,-583.08) 1(8989.59,-508.08) 1(8996.37,-2583.1) 1(9011.31,-2621.85) 1(9011.31,-2546.85) 1(9019.79,-549.33) 1(9019.79,-549.33) 1(9020.72,-538.08) 1(9020.72,-538.08) 1(9021.65,-560.58) 1(9021.65,-560.58) 1(9024.45,-568.08) 1(9024.45,-568.08) 1(9024.45,-525.58) 1(9024.45,-525.58) 1(9029.12,-518.08) 1(9029.12,-518.08) 1(9030.05,-575.58) 1(9030.05,-575.58) 1(9035.65,-511.83) 1(9035.65,-511.83) 1(9036.59,-580.58) 1(9036.59,-580.58) 1(9043.12,-583.08) 1(9043.12,-583.08) 1(9044.05,-508.08) 1(9044.05,-508.08) 1(9047.11,-2621.85) 1(9047.11,-2621.85) 1(9047.11,-2546.85) 1(9047.11,-2546.85) 1(9049.65,-583.08) 1(9049.65,-583.08) 1(9051.52,-508.08) 1(9051.52,-508.08) 1(9056.19,-580.58) 1(9056.19,-580.58) 1(9058.05,-510.58) 1(9058.05,-510.58) 1(9061.79,-576.83) 1(9061.79,-576.83) 1(9063.65,-514.33) 1(9065.77,-2621.85) 1(9065.77,-2621.85) 1(9065.77,-2546.85) 1(9065.77,-2546.85) 1(9066.45,-571.83) 1(9073.24,-2618.1) 1(9073.24,-2618.1) 1(9073.24,-2550.6) 1(9073.24,-2550.6) 1(9078.84,-2613.1) 1(9078.84,-2613.1) 1(9078.84,-2555.6) 1(9078.84,-2555.6) 1(9083.51,-2605.6) 1(9083.51,-2605.6) 1(9083.51,-2563.1) 1(9083.51,-2563.1) 1(9087.24,-2596.85) 1(9087.24,-2596.85) 1(9087.24,-2571.85) 1(9087.24,-2571.85) 1(9088.17,-2584.35) 1(9088.17,-2584.35) 1(9099.45,-583.08) 1(9099.45,-583.08) 1(9099.45,-544.33) 1(9099.45,-508.08) 1(9099.45,-508.08) 1(9119.31,-2621.85) 1(9121.85,-544.33) 1(9127.71,-2595.6) 1(9136.8,-583.08) 1(9136.8,-508.08) 1(9142.64,-2546.85) 1(9142.64,-2546.85) 1(9157.57,-2595.6) 1(9165.97,-2621.85) 1(9196.17,-2621.85) 1(9196.17,-2546.85) 1(9196.17,-2546.85) 1(9239.11,-2621.85) 1(9239.11,-2621.85) 1(9239.11,-2546.85) 1(9244.8,-549.33) 1(9244.8,-549.33) 1(9245.73,-538.08) 1(9245.73,-538.08) 1(9246.66,-560.58) 1(9246.66,-560.58) 1(9249.46,-568.08) 1(9249.46,-568.08) 1(9249.46,-525.58) 1(9249.46,-525.58) 1(9254.13,-518.08) 1(9254.13,-518.08) 1(9255.06,-575.58) 1(9255.06,-575.58) 1(9260.66,-511.83) 1(9260.66,-511.83) 1(9261.6,-580.58) 1(9261.6,-580.58) 1(9268.13,-583.08) 1(9268.13,-583.08) 1(9269.06,-508.08) 1(9269.06,-508.08) 1(9269.31,-2588.1) 1(9269.31,-2588.1) 1(9270.24,-2576.85) 1(9270.24,-2576.85) 1(9271.17,-2599.35) 1(9271.17,-2599.35) 1(9273.97,-2606.85) 1(9273.97,-2606.85) 1(9273.97,-2564.35) 1(9273.97,-2564.35) 1(9274.66,-583.08) 1(9274.66,-583.08) 1(9276.53,-508.08) 1(9276.53,-508.08) 1(9278.64,-2556.85) 1(9278.64,-2556.85) 1(9279.57,-2614.35) 1(9279.57,-2614.35) 1(9281.2,-580.58) 1(9281.2,-580.58) 1(9283.06,-510.58) 1(9283.06,-510.58) 1(9285.17,-2550.6) 1(9285.17,-2550.6) 1(9286.11,-2619.35) 1(9286.11,-2619.35) 1(9286.8,-576.83) 1(9286.8,-576.83) 1(9288.66,-514.33) 1(9291.46,-571.83) 1(9292.64,-2621.85) 1(9292.64,-2621.85) 1(9293.57,-2546.85) 1(9293.57,-2546.85) 1(9299.17,-2621.85) 1(9299.17,-2621.85) 1(9301.04,-2546.85) 1(9301.04,-2546.85) 1(9305.71,-2619.35) 1(9305.71,-2619.35) 1(9307.57,-2549.35) 1(9307.57,-2549.35) 1(9311.31,-2615.6) 1(9311.31,-2615.6) 1(9313.17,-2553.1) 1(9315.97,-2610.6) 1(9317.93,-550.58) 1(9317.93,-550.58) 1(9317.93,-540.58) 1(9317.93,-540.58) 1(9319.8,-560.58) 1(9319.8,-560.58) 1(9319.8,-530.58) 1(9319.8,-530.58) 1(9323.53,-569.33) 1(9323.53,-569.33) 1(9323.53,-521.83) 1(9323.53,-521.83) 1(9329.13,-576.83) 1(9329.13,-576.83) 1(9329.13,-514.33) 1(9329.13,-514.33) 1(9335.66,-581.83) 1(9335.66,-581.83) 1(9335.66,-509.33) 1(9335.66,-509.33) 1(9343.13,-583.08) 1(9343.13,-583.08) 1(9343.13,-508.08) 1(9343.13,-508.08) 1(9348.97,-2621.85) 1(9348.97,-2621.85) 1(9348.97,-2583.1) 1(9348.97,-2546.85) 1(9348.97,-2546.85) 1(9350.6,-581.83) 1(9350.6,-581.83) 1(9350.6,-509.33) 1(9350.6,-509.33) 1(9357.13,-576.83) 1(9357.13,-576.83) 1(9357.13,-514.33) 1(9357.13,-514.33) 1(9362.73,-569.33) 1(9362.73,-569.33) 1(9362.73,-521.83) 1(9362.73,-521.83) 1(9366.46,-560.58) 1(9366.46,-560.58) 1(9366.46,-530.58) 1(9366.46,-530.58) 1(9368.33,-550.58) 1(9368.33,-550.58) 1(9368.33,-540.58) 1(9368.33,-540.58) 1(9371.37,-2583.1) 1(9386.31,-2621.85) 1(9386.31,-2546.85) 1(9396.66,-583.08) 1(9396.66,-508.08) 1(9396.66,-508.08) 1(9439.6,-583.08) 1(9439.6,-583.08) 1(9439.6,-508.08) 1(9471.66,-508.08) 1(9493.13,-583.08) 1(9493.13,-508.08) 1(9494.31,-2588.1) 1(9494.31,-2588.1) 1(9495.24,-2576.85) 1(9495.24,-2576.85) 1(9496.17,-2599.35) 1(9496.17,-2599.35) 1(9498.97,-2606.85) 1(9498.97,-2606.85) 1(9498.97,-2564.35) 1(9498.97,-2564.35) 1(9503.64,-2556.85) 1(9503.64,-2556.85) 1(9504.57,-2614.35) 1(9504.57,-2614.35) 1(9510.17,-2550.6) 1(9510.17,-2550.6) 1(9511.11,-2619.35) 1(9511.11,-2619.35) 1(9514.6,-508.08) 1(9517.64,-2621.85) 1(9517.64,-2621.85) 1(9518.57,-2546.85) 1(9518.57,-2546.85) 1(9524.17,-2621.85) 1(9524.17,-2621.85) 1(9526.04,-2546.85) 1(9526.04,-2546.85) 1(9530.71,-2619.35) 1(9530.71,-2619.35) 1(9532.57,-2549.35) 1(9532.57,-2549.35) 1(9536.31,-2615.6) 1(9536.31,-2615.6) 1(9538.17,-2553.1) 1(9540.97,-2610.6) 1(9549.46,-583.08) 1(9549.46,-546.83) 1(9549.46,-508.08) 1(9549.46,-508.08) 1(9567.44,-2589.35) 1(9567.44,-2589.35) 1(9567.44,-2579.35) 1(9567.44,-2579.35) 1(9569.31,-2599.35) 1(9569.31,-2599.35) 1(9569.31,-2569.35) 1(9569.31,-2569.35) 1(9572.8,-546.83) 1(9572.8,-546.83) 1(9572.8,-546.83) 1(9572.8,-508.08) 1(9572.8,-508.08) 1(9573.04,-2608.1) 1(9573.04,-2608.1) 1(9573.04,-2560.6) 1(9573.04,-2560.6) 1(9578.64,-2615.6) 1(9578.64,-2615.6) 1(9578.64,-2553.1) 1(9578.64,-2553.1) 1(9579.33,-543.08) 1(9579.33,-543.08) 1(9580.26,-511.83) 1(9580.26,-511.83) 1(9584.93,-536.83) 1(9584.93,-536.83) 1(9584.93,-516.83) 1(9584.93,-516.83) 1(9585.17,-2620.6) 1(9585.17,-2620.6) 1(9585.17,-2548.1) 1(9585.17,-2548.1) 1(9586.8,-583.08) 1(9586.8,-526.83) 1(9586.8,-526.83) 1(9592.64,-2621.85) 1(9592.64,-2621.85) 1(9592.64,-2546.85) 1(9592.64,-2546.85) 1(9600.11,-2620.6) 1(9600.11,-2620.6) 1(9600.11,-2548.1) 1(9600.11,-2548.1) 1(9606.64,-2615.6) 1(9606.64,-2615.6) 1(9606.64,-2553.1) 1(9606.64,-2553.1) 1(9612.24,-2608.1) 1(9612.24,-2608.1) 1(9612.24,-2560.6) 1(9612.24,-2560.6) 1(9615.97,-2599.35) 1(9615.97,-2599.35) 1(9615.97,-2569.35) 1(9615.97,-2569.35) 1(9617.84,-2589.35) 1(9617.84,-2589.35) 1(9617.84,-2579.35) 1(9617.84,-2579.35) 1(9617.93,-550.58) 1(9617.93,-550.58) 1(9617.93,-540.58) 1(9617.93,-540.58) 1(9619.8,-560.58) 1(9619.8,-560.58) 1(9619.8,-530.58) 1(9619.8,-530.58) 1(9623.53,-569.33) 1(9623.53,-569.33) 1(9623.53,-521.83) 1(9623.53,-521.83) 1(9629.13,-576.83) 1(9629.13,-576.83) 1(9629.13,-514.33) 1(9629.13,-514.33) 1(9635.66,-581.83) 1(9635.66,-581.83) 1(9635.66,-509.33) 1(9635.66,-509.33) 1(9643.13,-583.08) 1(9643.13,-583.08) 1(9643.13,-508.08) 1(9643.13,-508.08) 1(9646.17,-2621.85) 1(9646.17,-2546.85) 1(9646.17,-2546.85) 1(9650.6,-581.83) 1(9650.6,-581.83) 1(9650.6,-509.33) 1(9650.6,-509.33) 1(9657.13,-576.83) 1(9657.13,-576.83) 1(9657.13,-514.33) 1(9657.13,-514.33) 1(9662.73,-569.33) 1(9662.73,-569.33) 1(9662.73,-521.83) 1(9662.73,-521.83) 1(9666.46,-560.58) 1(9666.46,-560.58) 1(9666.46,-530.58) 1(9666.46,-530.58) 1(9668.33,-550.58) 1(9668.33,-550.58) 1(9668.33,-540.58) 1(9668.33,-540.58) 1(9689.11,-2621.85) 1(9689.11,-2621.85) 1(9689.11,-2546.85) 1(9699.46,-583.08) 1(9699.46,-583.08) 1(9699.46,-508.08) 1(9721.17,-2546.85) 1(9736.8,-583.08) 1(9742.64,-2621.85) 1(9742.64,-2546.85) 1(9764.11,-2546.85) 1(9798.97,-2621.85) 1(9798.97,-2585.6) 1(9798.97,-2546.85) 1(9798.97,-2546.85) 1(9822.31,-2585.6) 1(9822.31,-2585.6) 1(9822.31,-2585.6) 1(9822.31,-2546.85) 1(9822.31,-2546.85) 1(9828.84,-2581.85) 1(9828.84,-2581.85) 1(9829.77,-2550.6) 1(9829.77,-2550.6) 1(9834.44,-2575.6) 1(9834.44,-2575.6) 1(9834.44,-2555.6) 1(9834.44,-2555.6) 1(9836.31,-2621.85) 1(9836.31,-2565.6) 1(9836.31,-2565.6) 1(9867.44,-2589.35) 1(9867.44,-2589.35) 1(9867.44,-2579.35) 1(9867.44,-2579.35) 1(9869.31,-2599.35) 1(9869.31,-2599.35) 1(9869.31,-2569.35) 1(9869.31,-2569.35) 1(9873.04,-2608.1) 1(9873.04,-2608.1) 1(9873.04,-2560.6) 1(9873.04,-2560.6) 1(9878.64,-2615.6) 1(9878.64,-2615.6) 1(9878.64,-2553.1) 1(9878.64,-2553.1) 1(9885.17,-2620.6) 1(9885.17,-2620.6) 1(9885.17,-2548.1) 1(9885.17,-2548.1) 1(9892.64,-2621.85) 1(9892.64,-2621.85) 1(9892.64,-2546.85) 1(9892.64,-2546.85) 1(9900.11,-2620.6) 1(9900.11,-2620.6) 1(9900.11,-2548.1) 1(9900.11,-2548.1) 1(9906.64,-2615.6) 1(9906.64,-2615.6) 1(9906.64,-2553.1) 1(9906.64,-2553.1) 1(9912.24,-2608.1) 1(9912.24,-2608.1) 1(9912.24,-2560.6) 1(9912.24,-2560.6) 1(9915.97,-2599.35) 1(9915.97,-2599.35) 1(9915.97,-2569.35) 1(9915.97,-2569.35) 1(9917.84,-2589.35) 1(9917.84,-2589.35) 1(9917.84,-2579.35) 1(9917.84,-2579.35) 1(9948.97,-2621.85) 1(9948.97,-2621.85) 1(9948.97,-2546.85) 1(9986.31,-2621.85) 1(10728.18,-6456.37) 1(10728.18,-6449.7) 1(10728.18,-6449.7) 1(10730.68,-6483.03) 1(10730.68,-6483.03) 1(10733.18,-6406.37) 1(10733.18,-6406.37) 1(10740.68,-6513.04) 1(10740.68,-6513.04) 1(10740.68,-6383.03) 1(10740.68,-6383.03) 1(10745.68,-6433.03) 1(10745.68,-6433.03) 1(10753.18,-6359.7) 1(10753.18,-6359.7) 1(10758.18,-6533.04) 1(10758.18,-6533.04) 1(10760.68,-6419.7) 1(10760.68,-6419.7) 1(10770.68,-6343.03) 1(10770.68,-6343.03) 1(10778.18,-6539.7) 1(10778.18,-6539.7) 1(10780.68,-6413.04) 1(10780.68,-6413.04) 1(10788.18,-6339.7) 1(10788.18,-6339.7) 1(10795.68,-6533.04) 1(10795.68,-6533.04) 1(10798.18,-6419.7) 1(10798.18,-6419.7) 1(10805.68,-6346.36) 1(10805.68,-6346.36) 1(10810.68,-6516.37) 1(10810.68,-6516.37) 1(10810.68,-6433.03) 1(10810.68,-6433.03) 1(10818.18,-6363.03) 1(10820.68,-6496.37) 1(10820.68,-6496.37) 1(10820.68,-6453.03) 1(10820.68,-6453.03) 1(10823.18,-6476.37) 1(10823.18,-6476.37) 1(10878.18,8893.64) 1(10878.18,8900.31) 1(10878.18,8900.31) 1(10880.68,8866.98) 1(10880.68,8866.98) 1(10883.18,8943.64) 1(10883.18,8943.64) 1(10890.68,8836.97) 1(10890.68,8836.97) 1(10890.68,8966.98) 1(10890.68,8966.98) 1(10895.68,8916.98) 1(10895.68,8916.98) 1(10903.18,8990.31) 1(10903.18,8990.31) 1(10908.18,8816.97) 1(10908.18,8816.97) 1(10910.68,8930.31) 1(10910.68,8930.31) 1(10920.68,9006.98) 1(10920.68,9006.98) 1(10928.18,8810.31) 1(10928.18,8810.31) 1(10930.68,8936.97) 1(10930.68,8936.97) 1(10938.18,9010.31) 1(10938.18,9010.31) 1(10945.68,8816.97) 1(10945.68,8816.97) 1(10948.18,8930.31) 1(10948.18,8930.31) 1(10955.68,9003.64) 1(10955.68,9003.64) 1(10960.68,8833.64) 1(10960.68,8833.64) 1(10960.68,8916.98) 1(10960.68,8916.98) 1(10968.18,8986.98) 1(10970.68,8853.64) 1(10970.68,8853.64) 1(10970.68,8896.98) 1(10970.68,8896.98) 1(10973.18,8873.64) 1(10973.18,8873.64) 1(12560.68,-1749.7) 1(12560.68,-1749.7) 1(12560.68,-1726.37) 1(12560.68,-1726.37) 1(12565.68,-1776.37) 1(12565.68,-1776.37) 1(12565.68,-1706.37) 1(12565.68,-1706.37) 1(12573.18,-5089.7) 1(12573.18,-4989.7) 1(12573.18,-4889.7) 1(12575.68,-1799.7) 1(12575.68,-1799.7) 1(12575.68,-1683.03) 1(12575.68,-1683.03) 1(12590.68,-1819.7) 1(12590.68,-1819.7) 1(12590.68,-1663.03) 1(12590.68,-1663.03) 1(12605.68,-1649.7) 1(12605.68,-1649.7) 1(12608.18,-1833.04) 1(12608.18,-1833.04) 1(12620.68,7060.31) 1(12620.68,7060.31) 1(12620.68,7260.31) 1(12620.68,7260.31) 1(12625.68,-1639.7) 1(12625.68,-1639.7) 1(12628.18,960.3) 1(12628.18,1063.64) 1(12628.18,1160.3) 1(12628.18,1160.3) 1(12633.18,-1839.7) 1(12633.18,-1839.7) 1(12640.68,-1739.7) 1(12643.18,-1639.7) 1(12643.18,-1639.7) 1(12658.18,-1833.04) 1(12658.18,-1833.04) 1(12663.18,-1646.36) 1(12663.18,-1646.36) 1(12670.68,7060.31) 1(12670.68,7060.31) 1(12670.68,7260.31) 1(12670.68,7260.31) 1(12675.68,-1819.7) 1(12675.68,-1819.7) 1(12675.68,4010.31) 1(12675.68,4010.31) 1(12675.68,4113.65) 1(12675.68,4210.31) 1(12675.68,4210.31) 1(12678.18,-5089.7) 1(12678.18,-4989.7) 1(12678.18,-4889.7) 1(12678.18,-1659.7) 1(12688.18,1063.64) 1(12690.68,-1799.7) 1(12690.68,-1799.7) 1(12690.68,-1739.7) 1(12690.68,-1739.7) 1(12690.68,7070.31) 1(12690.68,7070.31) 1(12690.68,7250.31) 1(12690.68,7250.31) 1(12705.68,7083.64) 1(12705.68,7083.64) 1(12705.68,7236.98) 1(12705.68,7236.98) 1(12718.18,7103.64) 1(12718.18,7103.64) 1(12718.18,7216.98) 1(12718.18,7216.98) 1(12723.18,1160.3) 1(12728.18,7126.97) 1(12728.18,7126.97) 1(12728.18,7193.64) 1(12728.18,7193.64) 1(12730.68,7160.31) 1(12730.68,7160.31) 1(12735.68,4113.65) 1(12775.68,4010.31) 1(12775.68,4210.31)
